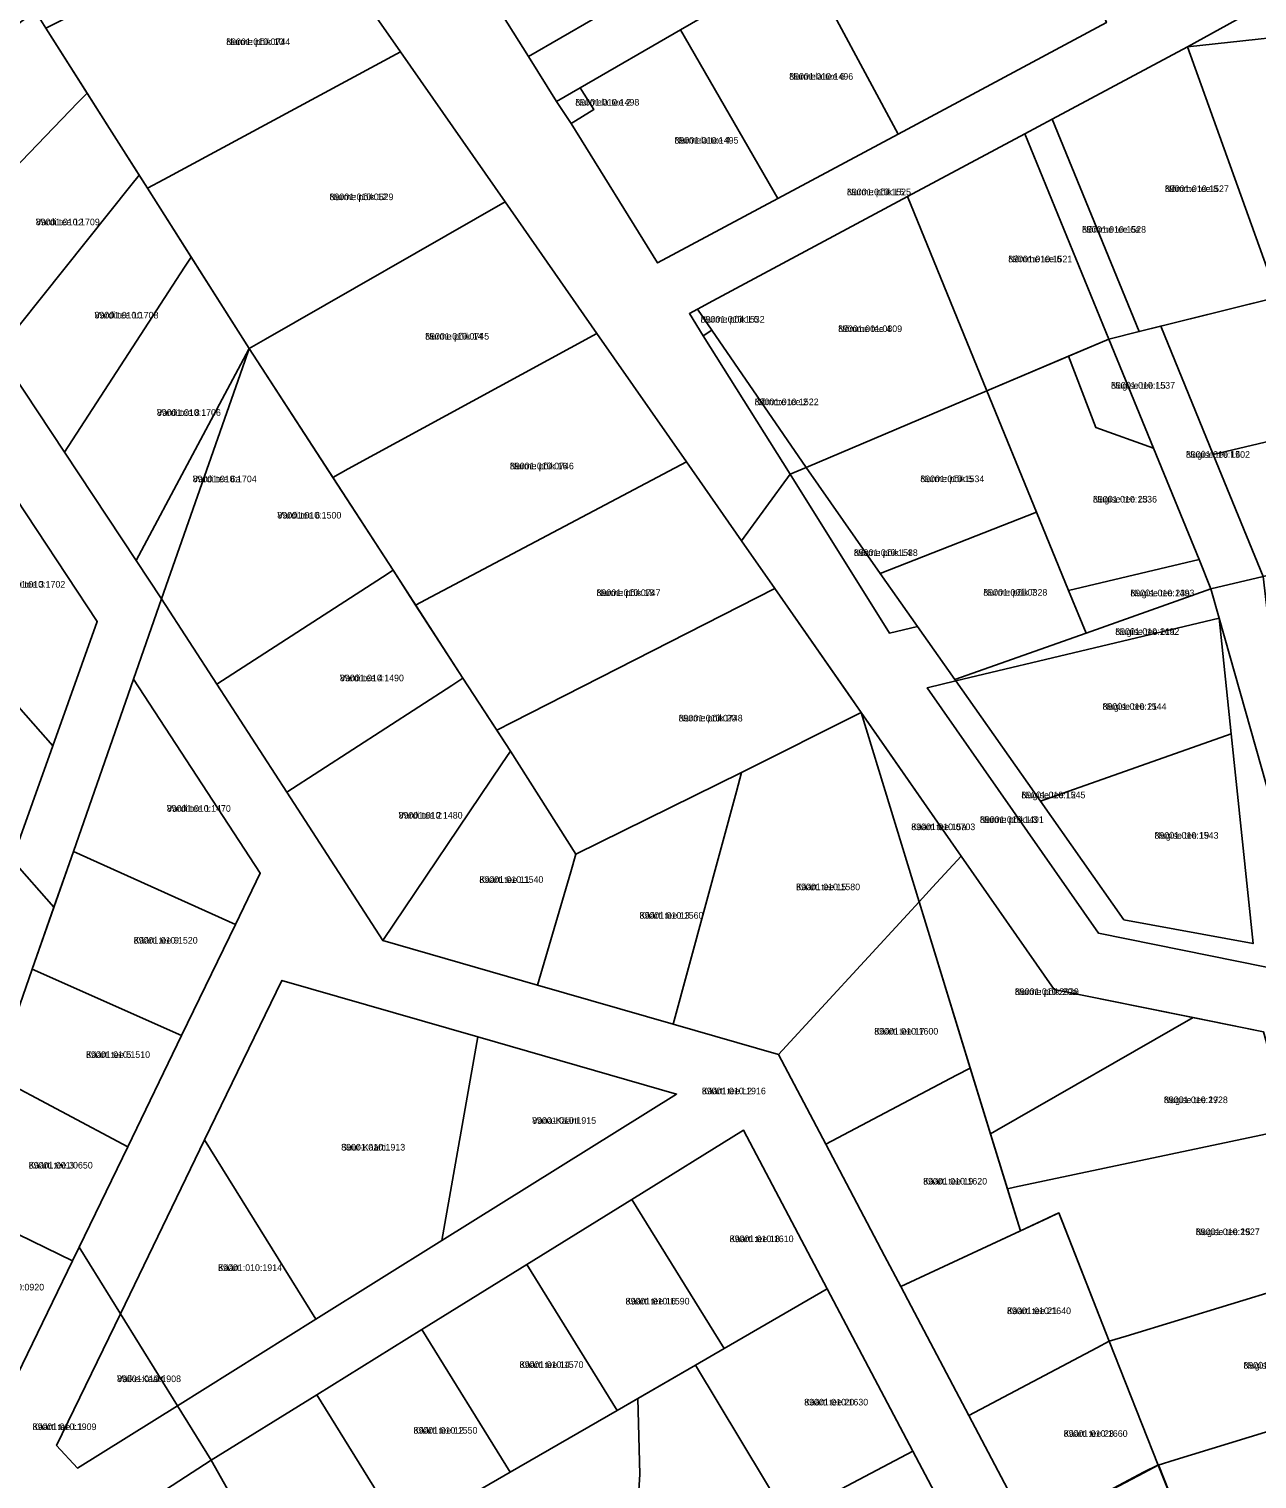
# Model space of a CAD drawing. Extents: x 526849 to 562296, y 6591741 to 6618546.
# Drawn here: x 546246.1 to 546524.3, y 6598270.9 to 6598599.5 of the extents above; entities that cross this region are included whole.
import ezdxf

# ---------------------------------------------------------------- set-up
doc = ezdxf.new("R2010")
doc.units = 0
for name, color, linetype in [('L_AADRESS', 7, 'Continuous'), ('PIIR', 7, 'Continuous'), ('TUNNUS', 7, 'Continuous')]:
    doc.layers.add(name, color=color, linetype=linetype)

msp = doc.modelspace()

# ---------------------------------------------------------------- linework, layer by layer
at = {"layer": 'PIIR'}
for points in [[(546345.4, 6598615.39), (546390.68, 6598642.86), (546403.25, 6598618.69), (546359.25, 6598593.27)], [(546421.69, 6598615.44), (546473.49, 6598645.37), (546490.21, 6598600.91), (546443.01, 6598575.64)], [(546249.9, 6598599.66), (546306.59, 6598628.27), (546308.31, 6598625.81), (546330.28, 6598594.29), (546276.64, 6598565.37), (546272.94, 6598563.37), (546264.35, 6598576.9)], [(546359.25, 6598593.27), (546403.25, 6598618.69), (546416.01, 6598626.06), (546421.69, 6598615.44), (546393.69, 6598599.27), (546370.98, 6598586.14), (546365.64, 6598583.06)], [(546393.69, 6598599.27), (546421.69, 6598615.44), (546443.01, 6598575.64), (546415.78, 6598561.05)], [(546508.58, 6598595.44), (546540.36, 6598613), (546543.44, 6598599.17)], [(546207.88, 6598573.16), (546247.42, 6598603.5), (546248.74, 6598601.5), (546249.9, 6598599.66), (546259.24, 6598584.94), (546257.16, 6598582.79), (546224.23, 6598548.61), (546209.82, 6598570.25)], [(546368.93, 6598578.07), (546374.06, 6598581.2), (546370.98, 6598586.14), (546393.69, 6598599.27), (546415.78, 6598561.05), (546388.54, 6598546.46)], [(546508.58, 6598595.44), (546543.44, 6598599.17), (546547.1, 6598582.74), (546555.43, 6598545.32), (546528.99, 6598538.72)], [(546295.97, 6598527.08), (546272.94, 6598563.37), (546276.64, 6598565.37), (546330.28, 6598594.29), (546353.97, 6598560.31), (546299.69, 6598529.21)], [(546477.95, 6598579.04), (546508.58, 6598595.44), (546528.99, 6598538.72), (546497.65, 6598530.88)], [(546195.44, 6598591.91), (546209.82, 6598570.25), (546224.23, 6598548.61), (546239.02, 6598526.32), (546254.17, 6598503.61), (546270.41, 6598479), (546276.14, 6598470.32), (546269.8, 6598452.15), (546256.14, 6598413.06), (546251.75, 6598400.5), (546242.29, 6598411.22), (546251.52, 6598437.05), (546261.57, 6598465.17), (546240.93, 6598496.48), (546227.38, 6598517.03), (546207.55, 6598547.12), (546200.89, 6598556.34), (546183.43, 6598582.93)], [(546259.24, 6598584.94), (546264.35, 6598576.9), (546271.03, 6598566.37), (546269.17, 6598564.03), (546239.02, 6598526.32), (546224.23, 6598548.61), (546257.16, 6598582.79)], [(546365.64, 6598583.06), (546370.98, 6598586.14), (546374.06, 6598581.2), (546368.93, 6598578.07)], [(546471.75, 6598575.71), (546477.95, 6598579.04), (546497.65, 6598530.88), (546490.78, 6598529.17)], [(546445.17, 6598561.48), (546471.75, 6598575.71), (546490.78, 6598529.17), (546463.16, 6598517.48)], [(546271.03, 6598566.37), (546272.94, 6598563.37), (546282.83, 6598547.79), (546281.35, 6598545.51), (546254.17, 6598503.61), (546239.02, 6598526.32), (546269.17, 6598564.03)], [(546295.97, 6598527.08), (546299.69, 6598529.21), (546353.97, 6598560.31), (546374.77, 6598530.47), (546318.43, 6598499.78), (546314.92, 6598497.86)], [(546400.84, 6598531.21), (546397.6, 6598535.97), (546401.02, 6598537.83), (546445.17, 6598561.48), (546463.16, 6598517.48), (546422.17, 6598500.09)], [(546282.83, 6598547.79), (546295.97, 6598527.08), (546294.68, 6598524.65), (546270.41, 6598479), (546254.17, 6598503.61), (546281.35, 6598545.51)], [(546502.55, 6598532.1), (546528.99, 6598538.72), (546555.43, 6598545.32), (546555.91, 6598543.19), (546562.5, 6598514.47), (546514.43, 6598503.06)], [(546395.72, 6598534.99), (546397.6, 6598535.97), (546400.84, 6598531.21), (546398.86, 6598529.97)], [(546398.86, 6598529.97), (546400.84, 6598531.21), (546422.17, 6598500.09), (546418.53, 6598498.55)], [(546490.78, 6598529.17), (546497.65, 6598530.88), (546502.55, 6598532.1), (546514.43, 6598503.06), (546525.73, 6598475.41), (546513.92, 6598472.6), (546511.21, 6598479.22), (546500.88, 6598504.47)], [(546314.92, 6598497.86), (546318.43, 6598499.78), (546374.77, 6598530.47), (546395.05, 6598501.38), (546337.24, 6598470.77), (546333.7, 6598468.9), (546328.58, 6598476.8)], [(546481.65, 6598525.3), (546490.78, 6598529.17), (546500.88, 6598504.47), (546487.8, 6598509.18)], [(546295.97, 6598527.08), (546294.97, 6598524.19), (546276.14, 6598470.32), (546270.41, 6598479), (546294.68, 6598524.65)], [(546276.14, 6598470.32), (546294.97, 6598524.19), (546295.97, 6598527.08), (546328.58, 6598476.8), (546326.19, 6598475.26), (546288.67, 6598450.97)], [(546463.16, 6598517.48), (546481.65, 6598525.3), (546487.8, 6598509.18), (546500.88, 6598504.47), (546511.21, 6598479.22), (546481.65, 6598472.21), (546474.37, 6598490)], [(546422.17, 6598500.09), (546463.16, 6598517.48), (546474.37, 6598490), (546438.99, 6598476.08)], [(546514.43, 6598503.06), (546562.5, 6598514.47), (546565.05, 6598503.73), (546569.32, 6598485.76), (546525.73, 6598475.41)], [(546333.7, 6598468.9), (546337.24, 6598470.77), (546395.05, 6598501.38), (546407.53, 6598483.49), (546415.08, 6598472.66), (546355.65, 6598442.38), (546352.09, 6598440.56), (546344.43, 6598452.34)], [(546407.53, 6598483.49), (546418.53, 6598498.55), (546441.05, 6598462.56), (546447.44, 6598464.06), (546455.88, 6598452.09), (546456.12, 6598451.74), (546449.63, 6598450.2), (546488.4, 6598394.6), (546538.84, 6598384.35), (546595.7, 6598374.62), (546595.9, 6598373.78), (546599.35, 6598359.25), (546543.27, 6598368.66), (546543.87, 6598366.54), (546545.38, 6598361.2), (546550.45, 6598343.26), (546534.69, 6598340.57), (546525.85, 6598372.2), (546478.4, 6598381.84), (546457.34, 6598412.05), (546434.65, 6598444.59), (546415.08, 6598472.66)], [(546418.53, 6598498.55), (546422.17, 6598500.09), (546438.99, 6598476.08), (546447.44, 6598464.06), (546441.05, 6598462.56)], [(546240.93, 6598496.48), (546261.57, 6598465.17), (546251.52, 6598437.05), (546218.05, 6598474.95)], [(546447.44, 6598464.06), (546438.99, 6598476.08), (546474.37, 6598490), (546481.65, 6598472.21), (546485.63, 6598462.59), (546455.88, 6598452.09)], [(546481.65, 6598472.21), (546511.21, 6598479.22), (546513.92, 6598472.6), (546485.63, 6598462.59)], [(546218.05, 6598474.95), (546251.52, 6598437.05), (546242.29, 6598411.22), (546231.57, 6598423.36), (546206.6, 6598451.65), (546200.06, 6598459.06)], [(546288.67, 6598450.97), (546326.19, 6598475.26), (546328.58, 6598476.8), (546344.43, 6598452.34), (546341.88, 6598450.69), (546304.51, 6598426.5)], [(546513.92, 6598472.6), (546525.73, 6598475.41), (546529.45, 6598443.6), (546532.94, 6598414.22), (546534.79, 6598398.7), (546515.8, 6598465.92)], [(546352.09, 6598440.56), (546355.65, 6598442.38), (546415.08, 6598472.66), (546431.75, 6598448.74), (546434.65, 6598444.59), (546407.56, 6598430.97), (546370.01, 6598412.45), (546355.18, 6598435.81)], [(546455.88, 6598452.09), (546485.63, 6598462.59), (546513.92, 6598472.6), (546515.8, 6598465.92), (546456.12, 6598451.74)], [(546449.63, 6598450.2), (546456.12, 6598451.74), (546475.29, 6598424.46), (546494.18, 6598397.57), (546523.47, 6598392.22), (546518.53, 6598439.74), (546515.8, 6598465.92), (546534.79, 6598398.7), (546537.67, 6598388.49), (546538.84, 6598384.35), (546488.4, 6598394.6)], [(546456.12, 6598451.74), (546515.8, 6598465.92), (546518.53, 6598439.74), (546475.29, 6598424.46)], [(546269.8, 6598452.15), (546298.5, 6598408.18), (546292.87, 6598396.55), (546256.14, 6598413.06)], [(546304.51, 6598426.5), (546341.88, 6598450.69), (546344.43, 6598452.34), (546355.18, 6598435.81), (546353.23, 6598432.91), (546326.28, 6598392.88)], [(546392.03, 6598373.96), (546406.39, 6598426.67), (546407.56, 6598430.97), (546434.65, 6598444.59), (546447.79, 6598401.66), (546445.15, 6598398.8), (546415.9, 6598367.09)], [(546440.94, 6598435.57), (546457.34, 6598412.05), (546450.84, 6598404.98), (546447.79, 6598401.66), (546434.65, 6598444.59)], [(546475.29, 6598424.46), (546518.53, 6598439.74), (546523.47, 6598392.22), (546494.18, 6598397.57)], [(546353.23, 6598432.91), (546355.18, 6598435.81), (546370.01, 6598412.45), (546368.84, 6598408.47), (546361.28, 6598382.81), (546326.28, 6598392.88)], [(546368.84, 6598408.47), (546370.01, 6598412.45), (546407.56, 6598430.97), (546406.39, 6598426.67), (546392.03, 6598373.96), (546361.28, 6598382.81)], [(546256.14, 6598413.06), (546292.87, 6598396.55), (546280.66, 6598371.35), (546246.84, 6598386.44)], [(546447.79, 6598401.66), (546450.84, 6598404.98), (546457.34, 6598412.05), (546478.4, 6598381.84), (546509.89, 6598375.44), (546465.36, 6598349.9), (546463.95, 6598349.09), (546459.38, 6598364.06)], [(546415.9, 6598367.09), (546445.15, 6598398.8), (546447.79, 6598401.66), (546459.35, 6598364), (546456.25, 6598362.37), (546426.63, 6598346.74)], [(546246.84, 6598386.44), (546280.66, 6598371.35), (546268.47, 6598346.17), (546238.37, 6598362.14)], [(546285.89, 6598347.74), (546303.39, 6598383.86), (546347.77, 6598371.09), (546339.65, 6598324.9), (546311.09, 6598307.07)], [(546463.95, 6598349.09), (546465.36, 6598349.9), (546509.89, 6598375.44), (546525.85, 6598372.2), (546532, 6598350.2), (546469.4, 6598337.01), (546467.79, 6598336.67)], [(546347.77, 6598371.09), (546392.84, 6598358.12), (546339.65, 6598324.9)], [(546439.97, 6598321.47), (546426.63, 6598346.74), (546456.25, 6598362.37), (546459.35, 6598364), (546468.43, 6598334.6), (546470.74, 6598327.12), (546443.65, 6598314.49)], [(546223.06, 6598336.31), (546238.37, 6598362.14), (546268.47, 6598346.17), (546257.43, 6598323.43), (546255.93, 6598320.34), (546225.21, 6598335.26)], [(546382.71, 6598334.23), (546408.01, 6598349.91), (546426.98, 6598313.95), (546403.63, 6598300.46)], [(546467.79, 6598336.67), (546469.4, 6598337.01), (546532, 6598350.2), (546542.12, 6598317.76), (546494.69, 6598303.27), (546490.86, 6598302.1), (546480.2, 6598329.33), (546479.47, 6598331.19), (546470.74, 6598327.12)], [(546266.79, 6598308.31), (546285.89, 6598347.74), (546311.09, 6598307.07), (546279.71, 6598287.47)], [(546214.11, 6598319.98), (546223.06, 6598336.31), (546225.21, 6598335.26), (546255.93, 6598320.34), (546241.19, 6598289.86), (546216.46, 6598317.41)], [(546358.9, 6598319.48), (546382.71, 6598334.23), (546403.63, 6598300.46), (546397.09, 6598296.68), (546379.38, 6598286.44)], [(546445.98, 6598310.07), (546443.65, 6598314.49), (546477.09, 6598330.07), (546479.47, 6598331.19), (546490.86, 6598302.1), (546488.03, 6598300.6), (546459.05, 6598285.31)], [(546206.41, 6598306.21), (546214.11, 6598319.98), (546216.46, 6598317.41), (546241.19, 6598289.86), (546255.93, 6598320.34), (546257.43, 6598323.43), (546266.79, 6598308.31), (546252.36, 6598278.5), (546257.11, 6598273.35), (546279.71, 6598287.47), (546287.35, 6598275.14), (546263.87, 6598259.89), (546271.56, 6598246.44), (546265.88, 6598241.7), (546240.54, 6598269.19), (546209.4, 6598302.97)], [(546335.1, 6598304.74), (546358.9, 6598319.48), (546379.38, 6598286.44), (546355.13, 6598272.42)], [(546501.97, 6598274.04), (546490.86, 6598302.1), (546494.69, 6598303.27), (546542.12, 6598317.76), (546551.41, 6598289.23), (546505.79, 6598275.22)], [(546397.09, 6598296.68), (546403.63, 6598300.46), (546426.98, 6598313.95), (546446.38, 6598277.17), (546417.92, 6598262.17)], [(546252.36, 6598278.5), (546266.79, 6598308.31), (546279.71, 6598287.47), (546257.11, 6598273.35)], [(546311.3, 6598289.99), (546335.1, 6598304.74), (546355.13, 6598272.42), (546339.68, 6598263.49), (546337.75, 6598262.37), (546331.51, 6598257.38)], [(546459.05, 6598285.31), (546488.03, 6598300.6), (546490.86, 6598302.1), (546501.97, 6598274.04), (546498.69, 6598272.31), (546473.04, 6598258.78)], [(546381.59, 6598224.76), (546384.48, 6598271.96), (546384.05, 6598289.14), (546397.09, 6598296.68), (546417.92, 6598262.17), (546424.21, 6598251.76), (546385.91, 6598226.61)], [(546287.35, 6598275.14), (546311.3, 6598289.99), (546331.51, 6598257.38), (546307.96, 6598238.54)], [(546381.17, 6598218.64), (546366.08, 6598216.45), (546339.68, 6598263.49), (546355.13, 6598272.42), (546379.38, 6598286.44), (546384.05, 6598289.14), (546384.48, 6598271.96), (546381.59, 6598224.76)], [(546513.12, 6598245.96), (546501.97, 6598274.04), (546505.79, 6598275.22), (546551.41, 6598289.23), (546560.71, 6598260.71), (546516.94, 6598247.14)], [(546286.1, 6598221.04), (546271.56, 6598246.44), (546263.87, 6598259.89), (546287.35, 6598275.14), (546307.96, 6598238.54)], [(546424.21, 6598251.76), (546417.92, 6598262.17), (546446.38, 6598277.17), (546463.18, 6598245.33), (546436.57, 6598231.29)], [(546473.04, 6598258.78), (546498.66, 6598272.4), (546502, 6598274.13), (546513.12, 6598245.96), (546514.96, 6598241.31), (546515.41, 6598240.02), (546490.14, 6598226.38), (546489.38, 6598227.82)]]:
    msp.add_lwpolyline(points, close=True, dxfattribs=at)
for points in [[(546540.36, 6598613), (546508.58, 6598595.44), (546477.95, 6598579.04), (546471.75, 6598575.71), (546445.17, 6598561.48), (546401.02, 6598537.83), (546397.6, 6598535.97), (546395.72, 6598534.99), (546398.86, 6598529.97), (546418.53, 6598498.55), (546407.53, 6598483.49), (546395.05, 6598501.38), (546374.77, 6598530.47), (546353.97, 6598560.31), (546330.28, 6598594.29), (546306.59, 6598628.27)], [(546345.4, 6598615.39), (546359.25, 6598593.27), (546365.64, 6598583.06), (546368.93, 6598578.07), (546388.54, 6598546.46), (546415.78, 6598561.05), (546443.01, 6598575.64), (546490.21, 6598600.91)], [(546463.18, 6598245.33), (546446.38, 6598277.17), (546426.98, 6598313.95), (546408.01, 6598349.91), (546382.71, 6598334.23), (546358.9, 6598319.48), (546335.1, 6598304.74), (546311.3, 6598289.99), (546287.35, 6598275.14), (546279.71, 6598287.47), (546311.09, 6598307.07), (546339.65, 6598324.9), (546392.84, 6598358.12), (546347.77, 6598371.09), (546303.39, 6598383.86), (546285.89, 6598347.74), (546266.79, 6598308.31), (546257.43, 6598323.43), (546268.47, 6598346.17), (546280.66, 6598371.35), (546292.87, 6598396.55), (546298.5, 6598408.18), (546269.8, 6598452.15), (546276.14, 6598470.32), (546288.67, 6598450.97), (546304.51, 6598426.5), (546326.28, 6598392.88), (546361.28, 6598382.81), (546392.03, 6598373.96), (546415.9, 6598367.09), (546426.63, 6598346.74), (546439.97, 6598321.47), (546443.65, 6598314.49), (546445.98, 6598310.07), (546459.05, 6598285.31), (546473.04, 6598258.78)], [(546161.61, 6598249.69), (546181.28, 6598283.63), (546198.8, 6598314.19), (546208.11, 6598326.52), (546226.67, 6598359.85), (546224.68, 6598362.12), (546219.18, 6598368.36), (546201.2, 6598388.79), (546197.92, 6598392.51), (546200.13, 6598394.54), (546206.84, 6598400.69), (546230.83, 6598373.07), (546242.29, 6598411.22), (546251.75, 6598400.5), (546246.84, 6598386.44), (546238.37, 6598362.14), (546223.06, 6598336.31), (546214.11, 6598319.98), (546206.41, 6598306.21), (546194.5, 6598284.94), (546190.8, 6598277.39), (546185.6, 6598272.1), (546182.13, 6598264.66)]]:
    msp.add_lwpolyline(points, dxfattribs=at)

# ---------------------------------------------------------------- texts
at = {"layer": 'L_AADRESS'}
for s, p in [('Nurme põik 10', (546290.78, 6598595.82)), ('Nurmela tee 6', (546418.35, 6598587.97)), ('Nurmela tee 2', (546369.88, 6598582.11)), ('Nurmela tee 4', (546392.36, 6598573.5)), ('Nurme põik L5', (546431.44, 6598561.78)), ('Nõmme tee 8', (546503.47, 6598562.52)), ('Nurme põik 12', (546314.18, 6598560.68)), ('Vardi tee 12', (546247.63, 6598554.99)), ('Nõmme tee 6a', (546484.7, 6598553.29)), ('Nõmme tee 6', (546467.98, 6598546.6)), ('Vardi tee 10', (546260.93, 6598533.87)), ('Nurme põik L6', (546398.28, 6598532.93)), ('Nurme põik 14', (546335.85, 6598529.08)), ('Nõmme tee 4', (546429.43, 6598530.79)), ('Nugise tee L5', (546491.27, 6598517.96)), ('Nõmme tee 2', (546410.52, 6598514.22)), ('Vardi tee 8', (546275.07, 6598511.8)), ('Nurme põik 16', (546355.05, 6598499.68)), ('Nugise tee L4', (546508.25, 6598502.3)), ('Vardi tee 6a', (546283.19, 6598496.76)), ('Nurme põik 5', (546448.05, 6598496.78)), ('Nugise tee 23', (546487.18, 6598492.16)), ('Vardi tee 6', (546302.36, 6598488.53)), ('Nurme põik L4', (546432.98, 6598480.05)), ('Vardi tee 3', (546239.81, 6598472.87)), ('Nurme põik 18', (546374.69, 6598470.97)), ('Nurme põik 7', (546462.33, 6598471.04)), ('Nugise tee 23a', (546495.66, 6598470.9)), ('Nugise tee 21a', (546492.23, 6598462.17)), ('Vardi tee 4', (546316.54, 6598451.65)), ('Nugise tee 21', (546489.34, 6598445.19)), ('Nurme põik 20', (546393.3, 6598442.55)), ('Nugise tee L2', (546470.96, 6598425.14)), ('Vardi tee 1', (546277.32, 6598422.08)), ('Vardi tee 2', (546329.84, 6598420.54)), ('Käärti tee 15a', (546446, 6598417.92)), ('Nurme põik L3', (546461.55, 6598419.56)), ('Nugise tee 19', (546501.12, 6598415.98)), ('Käärti tee 11', (546348.14, 6598405.97)), ('Käärti tee 15', (546419.91, 6598404.31)), ('Käärti tee 13', (546384.42, 6598397.85)), ('Käärti tee 9', (546269.81, 6598392.21)), ('Nurme põik 20a', (546469.47, 6598380.57)), ('Käärti tee 17', (546437.62, 6598371.59)), ('Käärti tee 5', (546259.02, 6598366.31)), ('Käärti tee L2', (546398.55, 6598358.07)), ('Nugise tee 17', (546503.23, 6598356.06)), ('Vana-Käärti', (546360.09, 6598351.37)), ('Suur-Käärti', (546316.83, 6598345.32)), ('Käärti tee 3', (546246.03, 6598341.24)), ('Käärti tee 19', (546448.69, 6598337.61)), ('Nugise tee 15', (546510.47, 6598326.15)), ('Käärti tee 18', (546404.84, 6598324.56)), ('Käärti', (546288.94, 6598318.03)), ('Käärti tee 16', (546381.27, 6598310.43)), ('Käärti tee 21', (546467.7, 6598308.25)), ('Käärti tee 14', (546357.24, 6598296.05)), ('Nugise tee 13', (546521.28, 6598295.9)), ('Väike-Käärti', (546266.04, 6598292.84)), ('Käärti tee 20', (546421.74, 6598287.55)), ('Käärti tee L1', (546246.88, 6598281.97)), ('Käärti tee 12', (546333.21, 6598281.16)), ('Käärti tee 23', (546480.53, 6598280.44))]:
    msp.add_text(s, height=1.5, dxfattribs=at).set_placement(p)
at = {"layer": 'TUNNUS'}
for s, p in [('89001:010:0744', (546290.78, 6598595.82)), ('89001:010:1496', (546418.35, 6598587.97)), ('89001:010:1498', (546369.88, 6598582.11)), ('89001:010:1495', (546392.36, 6598573.5)), ('89001:010:1527', (546503.47, 6598562.52)), ('89001:010:0529', (546314.18, 6598560.68)), ('89001:010:1525', (546431.44, 6598561.78)), ('89001:010:1709', (546247.63, 6598554.99)), ('89001:010:1528', (546484.7, 6598553.29)), ('89001:010:1521', (546467.98, 6598546.6)), ('89001:010:1708', (546260.93, 6598533.87)), ('89001:010:1532', (546398.28, 6598532.93)), ('89001:010:0745', (546335.85, 6598529.08)), ('89001:001:0809', (546429.43, 6598530.79)), ('89001:010:1537', (546491.27, 6598517.96)), ('89001:010:1522', (546410.52, 6598514.22)), ('89001:010:1706', (546275.07, 6598511.8)), ('89001:010:0746', (546355.05, 6598499.68)), ('89001:010:1502', (546508.25, 6598502.3)), ('89001:010:1704', (546283.19, 6598496.76)), ('89001:010:1534', (546448.05, 6598496.78)), ('89001:010:1536', (546487.18, 6598492.16)), ('89001:010:1500', (546302.36, 6598488.53)), ('89001:010:1538', (546432.98, 6598480.05)), ('89001:010:1702', (546239.81, 6598472.87)), ('89001:010:0747', (546374.69, 6598470.97)), ('89001:001:0328', (546462.33, 6598471.04)), ('89001:010:1493', (546495.66, 6598470.9)), ('89001:010:1492', (546492.23, 6598462.17)), ('89001:010:1490', (546316.54, 6598451.65)), ('89001:010:1544', (546489.34, 6598445.19)), ('89001:010:0748', (546393.3, 6598442.55)), ('89001:010:1545', (546470.96, 6598425.14)), ('89001:010:1470', (546277.32, 6598422.08)), ('89001:010:1480', (546329.84, 6598420.54)), ('89001:010:0703', (546446, 6598417.92)), ('89001:010:1491', (546461.55, 6598419.56)), ('89001:010:1543', (546501.12, 6598415.98)), ('89001:010:1540', (546348.14, 6598405.97)), ('89001:010:1580', (546419.91, 6598404.31)), ('89001:010:1560', (546384.42, 6598397.85)), ('89001:010:1520', (546269.81, 6598392.21)), ('89001:010:2929', (546469.47, 6598380.57)), ('89001:010:1600', (546437.62, 6598371.59)), ('89001:010:1510', (546259.02, 6598366.31)), ('89001:010:1916', (546398.55, 6598358.07)), ('89001:010:2928', (546503.23, 6598356.06)), ('89001:010:1915', (546360.09, 6598351.37)), ('89001:010:1913', (546316.83, 6598345.32)), ('89001:001:0650', (546246.03, 6598341.24)), ('89001:010:1620', (546448.69, 6598337.61)), ('89001:010:2927', (546510.47, 6598326.15)), ('89001:010:1610', (546404.84, 6598324.56)), ('89001:010:1914', (546288.94, 6598318.03)), ('89001:010:0920', (546235.02, 6598313.61)), ('89001:010:1590', (546381.27, 6598310.43)), ('89001:010:1640', (546467.7, 6598308.25)), ('89001:010:1570', (546357.24, 6598296.05)), ('89001:010:7450', (546521.28, 6598295.9)), ('89001:010:1908', (546266.04, 6598292.84)), ('89001:010:1630', (546421.74, 6598287.55)), ('89001:010:1909', (546246.88, 6598281.97)), ('89001:010:1550', (546333.21, 6598281.16)), ('89001:010:1660', (546480.53, 6598280.44))]:
    msp.add_text(s, height=1.5, dxfattribs=at).set_placement(p)

doc.saveas('drawing.dxf')
